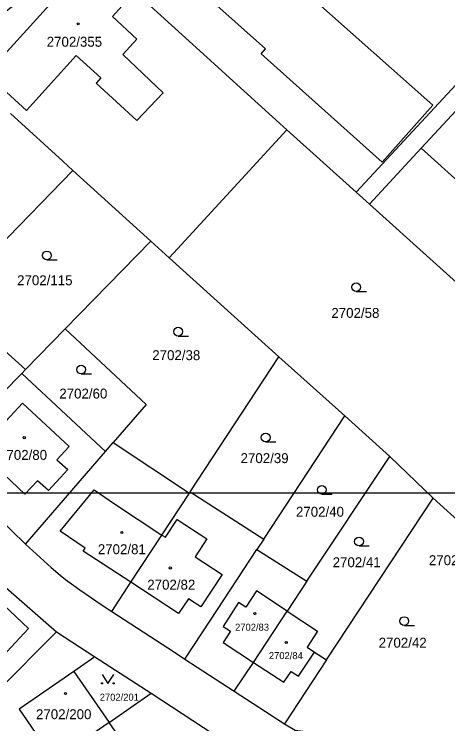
# Model space of a CAD drawing. Extents: x -496682 to -495776, y -1088797 to -1088018.
# Drawn here: x -496473.7 to -496399.5, y -1088500.7 to -1088379.3 of the extents above; entities that cross this region are included whole.
import ezdxf

# ---------------------------------------------------------------- set-up
doc = ezdxf.new("R2010")
doc.units = 0
for name, color, linetype in [('Hranice parcel', 7, 'Continuous'), ('Parcelní čísla', 7, 'Continuous'), ('Vnitřní kresba', 7, 'Continuous'), ('Vrstva 63', 7, 'Continuous'), ('Značky budov', 7, 'Continuous'), ('Značky kultur', 7, 'Continuous')]:
    doc.layers.add(name, color=color, linetype=linetype)

msp = doc.modelspace()

# ---------------------------------------------------------------- linework, layer by layer
at = {"layer": 'Hranice parcel'}
for p, q in [((-496415.13, -1088409.73), (-496376.05, -1088367.51)), ((-496426.99, -1088399.03), (-496415.13, -1088409.73)), ((-496463.6, -1088406), (-496485.14, -1088428.06)), ((-496450.29, -1088418.11), (-496464.95, -1088433.12)), ((-496447.16, -1088420.94), (-496450.29, -1088418.11)), ((-496428.41, -1088437.89), (-496447.16, -1088420.94)), ((-496471.71, -1088440.06), (-496485.14, -1088428.06)), ((-496464.95, -1088433.12), (-496471.71, -1088440.06)), ((-496443.54, -1088460.99), (-496428.41, -1088437.89)), ((-496417.08, -1088447.98), (-496428.41, -1088437.89)), ((-496471.71, -1088440.06), (-496472.38, -1088440.74)), ((-496472.38, -1088440.74), (-496475.55, -1088443.98)), ((-496472.38, -1088440.74), (-496458.05, -1088454.11)), ((-496430.97, -1088469.11), (-496417.08, -1088447.98)), ((-496409.38, -1088454.98), (-496417.08, -1088447.98)), ((-496458.05, -1088454.11), (-496456.7, -1088452.55)), ((-496456.7, -1088452.55), (-496443.69, -1088461.21)), ((-496471.75, -1088469.95), (-496458.05, -1088454.11)), ((-496486.71, -1088455.42), (-496471.75, -1088469.95)), ((-496423.57, -1088476.29), (-496409.38, -1088454.98)), ((-496401.99, -1088462.09), (-496409.38, -1088454.98)), ((-496443.69, -1088461.21), (-496443.54, -1088460.99)), ((-496443.54, -1088460.99), (-496430.97, -1088469.11)), ((-496420.23, -1088489.77), (-496401.99, -1088462.09)), ((-496390.64, -1088472.36), (-496401.99, -1088462.09)), ((-496430.97, -1088469.11), (-496432.15, -1088470.9)), ((-496432.15, -1088470.9), (-496423.57, -1088476.29)), ((-496480.12, -1088473.09), (-496466.41, -1088484.97)), ((-496423.57, -1088476.29), (-496426.98, -1088481.41)), ((-496480.76, -1088499.32), (-496466.41, -1088484.97)), ((-496466.41, -1088484.97), (-496459.85, -1088489.23)), ((-496459.85, -1088489.23), (-496450.23, -1088495.49)), ((-496444.46, -1088489.63), (-496436, -1088495.13)), ((-496420.23, -1088489.77), (-496427.43, -1088500.69)), ((-496457.42, -1088500.49), (-496450.23, -1088495.49)), ((-496450.23, -1088495.49), (-496437.15, -1088504)), ((-496436, -1088495.13), (-496427.43, -1088500.69))]:
    msp.add_line(p, q, dxfattribs=at)
for points in [[(-496468.73, -1088361.18), (-496438.82, -1088388.34), (-496436.83, -1088390.15), (-496426.99, -1088399.03)], [(-496458.81, -1088390.16), (-496459.62, -1088391.05), (-496452.7, -1088397.45), (-496448.2, -1088392.71), (-496455.1, -1088386.16), (-496452.66, -1088383.51), (-496456.87, -1088379.65), (-496455.18, -1088377.81), (-496462.05, -1088371.53), (-496462.96, -1088372.53), (-496463.92, -1088371.65), (-496464.44, -1088372.21), (-496465.37, -1088371.11), (-496483.02, -1088385.08), (-496478.41, -1088389.5), (-496471.58, -1088395.72), (-496463.03, -1088386.33), (-496458.81, -1088390.16)], [(-496474.27, -1088396.26), (-496465.34, -1088404.42), (-496463.6, -1088406)], [(-496426.99, -1088399.03), (-496445.74, -1088419.4), (-496447.16, -1088420.94)], [(-496450.29, -1088418.11), (-496458.79, -1088410.38), (-496463.6, -1088406)], [(-496415.13, -1088409.73), (-496412.88, -1088411.76), (-496391.09, -1088431.4)], [(-496464.95, -1088433.12), (-496451.1, -1088446.07), (-496456.7, -1088452.55)], [(-496456.97, -1088481.48), (-496453.7, -1088476.48), (-496448.39, -1088468.4), (-496443.69, -1088461.21)], [(-496471.75, -1088469.95), (-496467.34, -1088473.97), (-496465.8, -1088475.27), (-496464.87, -1088476.01), (-496462.43, -1088477.79), (-496460.45, -1088479.15), (-496458.77, -1088480.31), (-496456.97, -1088481.48)], [(-496444.46, -1088489.63), (-496440.08, -1088483), (-496432.15, -1088470.9)], [(-496477.23, -1088490.95), (-496480.8, -1088494.89), (-496480.96, -1088494.74), (-496482.79, -1088496.66), (-496486.16, -1088493.39), (-496484.58, -1088491.75), (-496488.65, -1088487.95), (-496478.73, -1088477.31), (-496471.2, -1088484.41), (-496474.93, -1088488.41)], [(-496436, -1088495.13), (-496432.72, -1088490.21), (-496426.98, -1088481.41)], [(-496426.98, -1088481.41), (-496421.75, -1088484.85), (-496423.56, -1088487.61), (-496422.3, -1088488.43), (-496420.23, -1088489.77)], [(-496456.97, -1088481.48), (-496446.26, -1088488.46), (-496444.46, -1088489.63)], [(-496459.85, -1088489.23), (-496463.48, -1088491.75), (-496457.42, -1088500.49)], [(-496457.42, -1088500.49), (-496466.76, -1088506.96), (-496469.49, -1088509.17)], [(-496465.53, -1088511.75), (-496464.43, -1088513.34), (-496463.02, -1088512.35), (-496460.32, -1088516.24), (-496450.98, -1088509.77), (-496457.42, -1088500.49)], [(-496427.43, -1088500.69), (-496425.57, -1088501.8), (-496381.96, -1088507.33)]]:
    msp.add_lwpolyline(points, dxfattribs=at)
at = {"layer": 'Vnitřní kresba'}
for p, q in [((-496404.03, -1088402.17), (-496375.12, -1088370.85)), ((-496478.41, -1088389.5), (-496463.48, -1088373.09)), ((-496430.67, -1088385.21), (-496442.28, -1088374.81)), ((-496422.76, -1088376.41), (-496402.05, -1088394.84)), ((-496431.4, -1088386.04), (-496430.67, -1088385.21)), ((-496410.7, -1088404.57), (-496431.4, -1088386.04)), ((-496402.05, -1088394.84), (-496410.7, -1088404.57)), ((-496412.88, -1088411.76), (-496404.03, -1088402.17)), ((-496391.38, -1088413.68), (-496404.03, -1088402.17)), ((-496479.76, -1088453.88), (-496472.22, -1088445.82)), ((-496472.22, -1088445.82), (-496464.24, -1088453.27)), ((-496464.24, -1088453.27), (-496466.36, -1088455.54)), ((-496471.83, -1088461.4), (-496479.76, -1088453.88)), ((-496466.36, -1088455.54), (-496464.46, -1088457.16)), ((-496464.46, -1088457.16), (-496467.81, -1088460.76)), ((-496469.7, -1088459.11), (-496471.83, -1088461.4)), ((-496467.81, -1088460.76), (-496469.7, -1088459.11)), ((-496465.78, -1088467.74), (-496459.95, -1088460.67)), ((-496459.95, -1088460.67), (-496456.51, -1088463.09)), ((-496456.51, -1088463.09), (-496448.39, -1088468.4)), ((-496447.8, -1088468.79), (-496445.8, -1088465.72)), ((-496445.8, -1088465.72), (-496440.68, -1088469.07)), ((-496461.49, -1088470.63), (-496465.78, -1088467.74)), ((-496448.39, -1088468.4), (-496447.8, -1088468.79)), ((-496440.68, -1088469.07), (-496442.69, -1088472.14)), ((-496461.86, -1088471.14), (-496461.49, -1088470.63)), ((-496453.7, -1088476.48), (-496461.86, -1088471.14)), ((-496442.69, -1088472.14), (-496438.1, -1088475.15)), ((-496438.1, -1088475.15), (-496441.72, -1088480.68)), ((-496445.54, -1088481.82), (-496453.7, -1088476.48)), ((-496432.21, -1088477.96), (-496434.04, -1088480.74)), ((-496426.98, -1088481.41), (-496432.21, -1088477.96)), ((-496443.85, -1088479.3), (-496445.54, -1088481.82)), ((-496441.72, -1088480.68), (-496443.85, -1088479.3)), ((-496435.28, -1088479.92), (-496437.91, -1088484.07)), ((-496434.04, -1088480.74), (-496435.28, -1088479.92)), ((-496436.67, -1088484.88), (-496437.93, -1088486.8)), ((-496437.91, -1088484.07), (-496436.67, -1088484.88)), ((-496437.93, -1088486.8), (-496432.72, -1088490.21)), ((-496425.03, -1088492.56), (-496422.3, -1088488.43)), ((-496432.72, -1088490.21), (-496427.51, -1088493.61)), ((-496463.48, -1088491.75), (-496472.82, -1088498.22)), ((-496427.51, -1088493.61), (-496426.29, -1088491.74)), ((-496426.29, -1088491.74), (-496425.03, -1088492.56)), ((-496472.82, -1088498.22), (-496469.32, -1088503.27))]:
    msp.add_line(p, q, dxfattribs=at)
at = {"layer": 'Vrstva 63'}
msp.add_lwpolyline([(-496137.35, -1088164.24), (-496137.35, -1088461.24), (-496557.35, -1088461.24), (-496557.35, -1088164.24)], close=True, dxfattribs=at)
at = {"layer": 'Značky budov'}
for centre in [(-496462.71, -1088380.92), (-496471.93, -1088451.74), (-496455.23, -1088467.98), (-496446.95, -1088474.04), (-496432.51, -1088481.85), (-496427.11, -1088486.78), (-496464.89, -1088495.53)]:
    msp.add_circle(centre, 0.175, dxfattribs=at)
at = {"layer": 'Značky kultur'}
for p, q in [((-496468.06, -1088421.29), (-496466.31, -1088421.29)), ((-496415.16, -1088426.73), (-496413.41, -1088426.73)), ((-496445.61, -1088434.34), (-496443.86, -1088434.34)), ((-496462.21, -1088440.84), (-496460.46, -1088440.84)), ((-496430.64, -1088452.47), (-496428.89, -1088452.47)), ((-496421.02, -1088461.42), (-496419.27, -1088461.42)), ((-496414.67, -1088470.25), (-496412.92, -1088470.25)), ((-496406.93, -1088483.88), (-496405.18, -1088483.88))]:
    msp.add_line(p, q, dxfattribs=at)
msp.add_lwpolyline([(-496458.63, -1088492.29), (-496457.63, -1088493.79), (-496456.63, -1088492.29)], dxfattribs=at)
for centre, radius in [((-496468.06, -1088420.54), 0.75), ((-496415.16, -1088425.98), 0.75), ((-496445.61, -1088433.59), 0.75), ((-496462.21, -1088440.09), 0.75), ((-496430.64, -1088451.72), 0.75), ((-496421.02, -1088460.67), 0.75), ((-496414.67, -1088469.5), 0.75), ((-496406.93, -1088483.13), 0.75), ((-496458.63, -1088493.79), 0.1), ((-496456.63, -1088493.79), 0.1)]:
    msp.add_circle(centre, radius, dxfattribs=at)

# ---------------------------------------------------------------- texts
at = {"layer": 'Parcelní čísla'}
for s, height, p in [('2702/355', 1.7, (-496468.1, -1088384.83)), ('2702/115', 1.7, (-496473.16, -1088425.65)), ('2702/58', 1.7, (-496419.4, -1088431.24)), ('2702/38', 1.7, (-496450.04, -1088438.47)), ('2702/60', 1.7, (-496465.94, -1088445.04)), ('2702/80', 1.7, (-496476.25, -1088455.54)), ('2702/39', 1.7, (-496434.93, -1088456.09)), ('2702/40', 1.7, (-496425.46, -1088465.27)), ('2702/81', 1.7, (-496459.35, -1088471.68)), ('2702/41', 1.7, (-496419.18, -1088473.91)), ('2702/487', 1.7, (-496402.72, -1088473.56)), ('2702/82', 1.7, (-496450.89, -1088477.75)), ('2702/83', 1.2, (-496435.87, -1088484.78)), ('2702/42', 1.7, (-496411.31, -1088487.68)), ('2702/84', 1.2, (-496430.09, -1088489.64)), ('2702/201', 1.2, (-496459.02, -1088496.76)), ('2702/200', 1.7, (-496469.93, -1088499.92))]:
    msp.add_text(s, height=height, dxfattribs=at).set_placement(p)

doc.saveas('drawing.dxf')
